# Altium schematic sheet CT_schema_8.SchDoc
size 308 x 210 mm
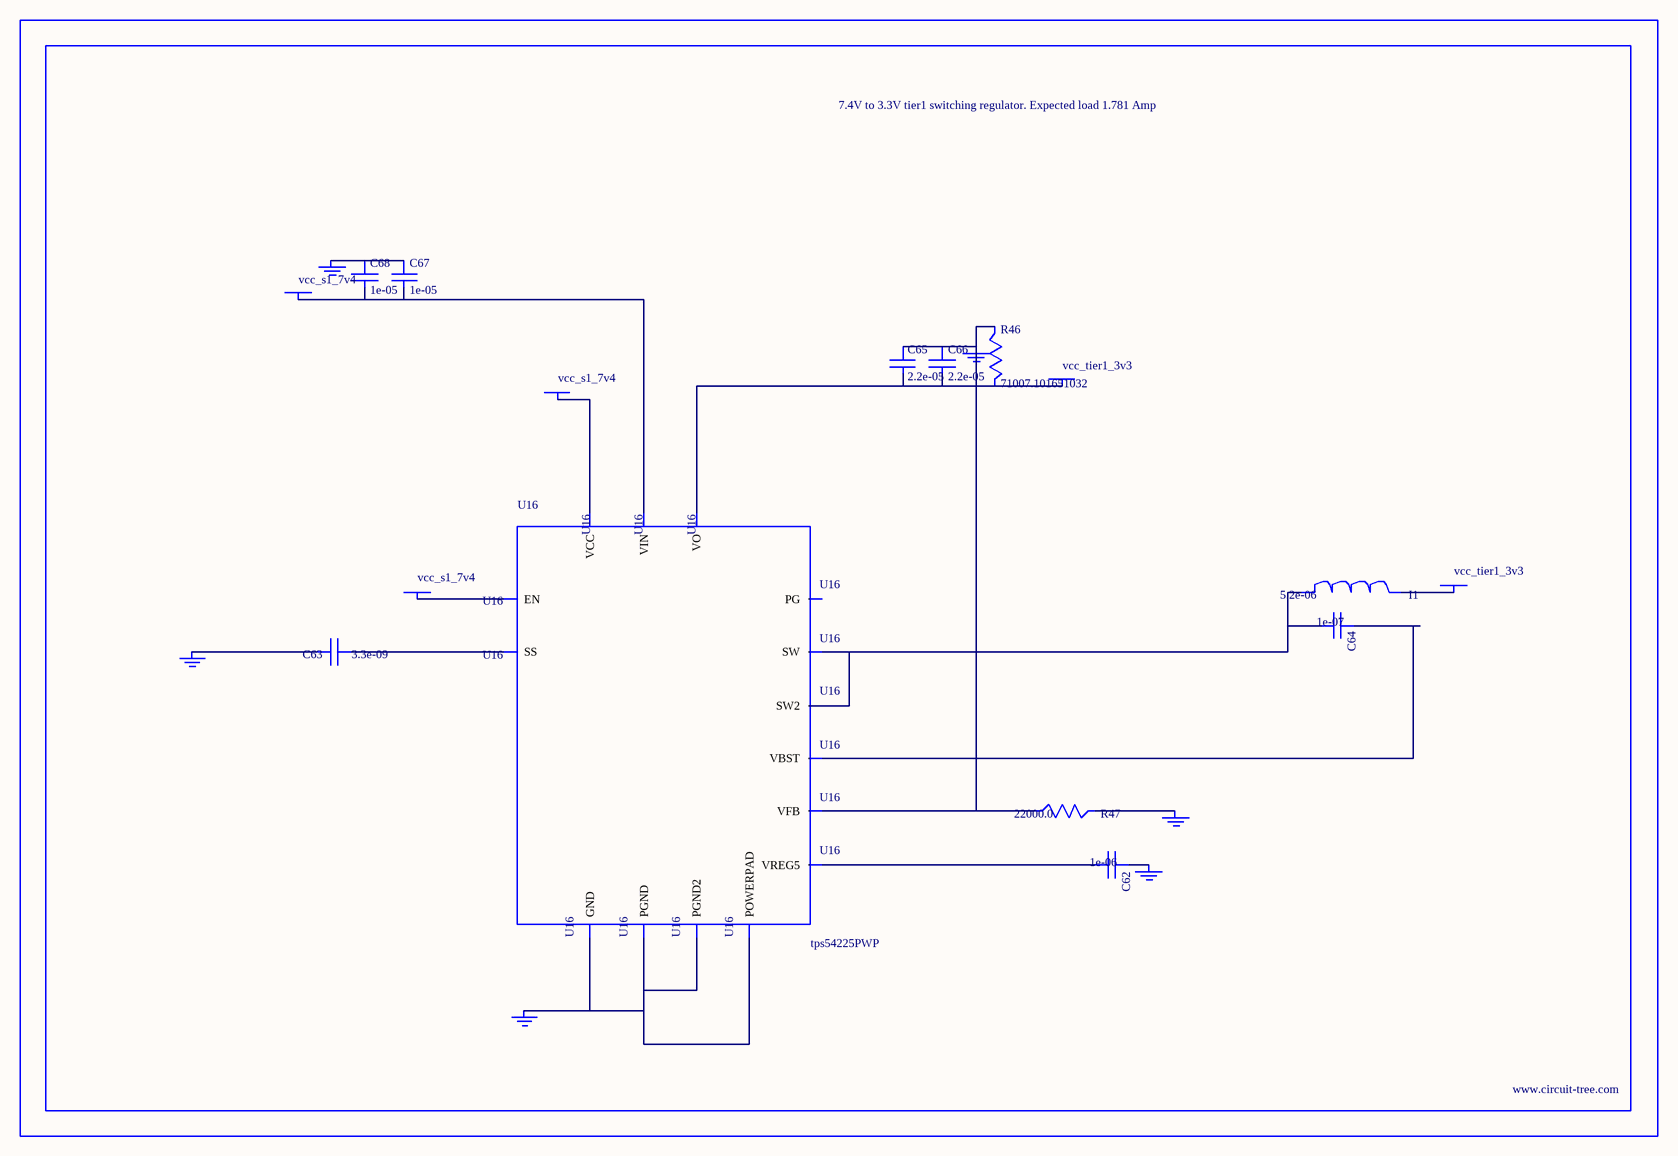
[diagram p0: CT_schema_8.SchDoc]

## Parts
BORDER7  (no value)
C62  1e-06  [C0603]
C63  3.3e-09  [C0402]
C64  1e-07  [C0402]
C65  2.2e-05  [C1210]
C66  2.2e-05  [C1210]
C67  1e-05  [C1206]
C68  1e-05  [C1206]
GND_INSTANCE_7_0  (no value)
GND_INSTANCE_7_1  (no value)
GND_INSTANCE_7_2  (no value)
GND_INSTANCE_7_3  (no value)
GND_INSTANCE_7_4  (no value)
GND_INSTANCE_7_5  (no value)
I1  5.2e-06  [DR1040]
POWER_INSTANCE_7_0  vcc_tier1_3v3
POWER_INSTANCE_7_1  vcc_s1_7v4
POWER_INSTANCE_7_2  vcc_tier1_3v3
POWER_INSTANCE_7_3  vcc_s1_7v4
POWER_INSTANCE_7_4  vcc_s1_7v4
R46  71007.101651032  [R0603]
R47  22000.0  [R0603]
U16  tps54225PWP  [HTSSOP14]

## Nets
NetC62_1: C62.1 GND_INSTANCE_7_2.0(GND)
NetC62_2: C62.2 U16.3(VREG5)
NetC63_1: C63.1 U16.4(SS)
NetC63_2: C63.2 GND_INSTANCE_7_3.0(GND)
NetC64_1: C64.1 U16.12(VBST)
NetC64_2: C64.2 I1.1 U16.10(SW) U16.11(SW2)
NetC65_1: C65.1 C66.1 GND_INSTANCE_7_0.0(GND) R46.1 R47.1 U16.2(VFB)
NetC65_2: C65.2 C66.2 POWER_INSTANCE_7_0.0(PWR) R46.2 U16.1(VO)
NetC67_1: C67.1 C68.1 GND_INSTANCE_7_5.0(GND)
NetC67_2: C67.2 C68.2 POWER_INSTANCE_7_3.0(PWR) U16.13(VIN)
NetGND_INSTANCE_7_1_0: GND_INSTANCE_7_1.0(GND) R47.2
NetGND_INSTANCE_7_4_0: GND_INSTANCE_7_4.0(GND) U16.5(GND) U16.8(PGND) U16.9(PGND2) U16.15(POWERPAD)
NetI1_2: I1.2 POWER_INSTANCE_7_2.0(PWR)
NetPOWER_INSTANCE_7_1_0: POWER_INSTANCE_7_1.0(PWR) U16.7(EN)
NetPOWER_INSTANCE_7_4_0: POWER_INSTANCE_7_4.0(PWR) U16.14(VCC)

Not connected (* = marked no-connect by the designer): U16 6(PG)

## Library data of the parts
BORDER7 = BORDER_PAGE7
C62 = C0603C105K3RACTU
C63 = C0402C332K3RAC
C64 = C0402C104K3RACTU
C65 C66 = GRM32ER61E226ME15L
C67 C68 = C1206C106K3RACTU
GND_INSTANCE_7_0-GND_INSTANCE_7_5 = GND
I1 = DR1040-5R2-R
POWER_INSTANCE_7_0-POWER_INSTANCE_7_4 = PWR
R46 = R46
R47 = RC0603JR-0722KL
